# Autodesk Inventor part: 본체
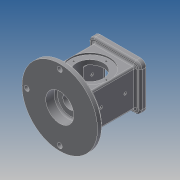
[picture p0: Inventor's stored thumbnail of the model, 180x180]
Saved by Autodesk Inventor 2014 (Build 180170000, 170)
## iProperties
Created: 2019-08
Part Number: 본체
Material: Generic
Document SubType Name: Modeling
Designer: kb542
Density: 1 g/cm^3
Appearance: Default
Author: kb542
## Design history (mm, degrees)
sketch "스케치1"
  geometry: C1 r 67.5 at (0, 0); 1 further point
  constraints: 1 centre point, 1 coincident
  dimensions: "d0" = 135 diameter of C1
extrude "돌출1" new body sketch "스케치1" distance "d1" = 10; taper "d2" = 0 deg
sketch "스케치2"
  geometry: L1 (-37, -33)-(37, -33); L2 (37, -33)-(37, 33); L3 (37, 33)-(-37, 33); L4 (-37, 33)-(-37, -33); L5 (-37, -33)-(37, 33); L6 (37, -33)-(-37, 33); C1 r 67.5 at (0, 0) reference
  constraints: 12 end point, 2 midpoint, 2 parallel, 1 horizontal, 1 perpendicular
  dimensions: "d3" = 74 distance of L2.end L3.end; "d4" = 66 distance of L1.end L2.end
node "작업 평면1"
sketch "스케치3" dims "d6" = 118
  geometry: 3 further points
  constraints: 2 horizontal alignment, 1 coincident, 2 other
feature "엠보싱1" sketch "스케치3" dims "d7" = 0.5, "d8" = 0
extrude "돌출2" join sketch "스케치2" distance "d9" = 98; taper "d10" = 0 deg
sketch "스케치4"
  geometry: L1 (-37, -33)-(37, -33) reference; L2 (37, -33)-(37, 33) reference; L3 (37, 33)-(-37, 33) reference; L4 (-37, 33)-(-37, -33) reference; L5 (-46, -41)-(46, -41); L6 (46, -41)-(46, 41); L7 (46, 41)-(-46, 41); L8 (-46, 41)-(-46, -41); L9 (-46, -41)-(46, 41); L10 (46, -41)-(-46, 41); 1 further point
  constraints: 12 end point, 2 midpoint, 2 parallel, 1 horizontal, 1 perpendicular
  dimensions: "d11" = 92 distance of L6.end L7.end; "d12" = 82 distance of L5.end L6.end
extrude "돌출3" join sketch "스케치4" distance "d13" = 10; taper "d14" = 0 deg
sketch "스케치5"
  geometry: 2 further points
  constraints: 1 vertical alignment
  dimensions: "d15" = 54 distance of point (37, -10) point (37, 44)
hole "구멍1" sketch "스케치5" at (37, 44) diameter "d16" = 48; stored, may be unused: countersink angle "d20" = 90 deg, drill point angle "d22" = 118 deg; dims "d17" = 6, "d18" = 4, "d19" = 2, "d21" = 8
sketch "스케치6"
  geometry: C1 r 24 at (37, 44) reference; 2 further points
  constraints: 1 coincident
hole "구멍2" sketch "스케치6" at (37, 44) diameter "d23" = 70; stored, may be unused: countersink angle "d27" = 90 deg, drill point angle "d29" = 0 deg; dims "d24" = 6, "d25" = 4, "d26" = 2, "d28" = 3
sketch "스케치7"
  geometry: C1 r 24 at (37, 44) reference; 2 further points
  constraints: 1 coincident
hole "구멍3" sketch "스케치7" at (37, 44) diameter "d30" = 70; stored, may be unused: countersink angle "d34" = 90 deg, drill point angle "d36" = 0 deg; dims "d31" = 6, "d32" = 4, "d33" = 2, "d35" = 3
sketch "스케치8"
  geometry: C1 r 67.5 at (0, 0) reference; 1 further point
  constraints: 1 coincident
hole "구멍4" sketch "스케치8" at (0, 0) diameter "d37" = 25; stored, may be unused: countersink angle "d41" = 90 deg, drill point angle "d43" = 118 deg; dims "d38" = 6, "d39" = 4, "d40" = 2, "d42" = 3
sketch "스케치9"
  geometry: C1 r 67.5 at (0, 0) reference; 1 further point
  constraints: 1 coincident
hole "구멍5" sketch "스케치9" at (0, 0) diameter "d44" = 50; stored, may be unused: countersink angle "d48" = 90 deg, drill point angle "d50" = 0 deg; dims "d45" = 6, "d46" = 4, "d47" = 2, "d49" = 18
sketch "스케치10"
  geometry: L1 (-22, -22)-(22, -22); L2 (22, -22)-(22, 22); L3 (22, 22)-(-22, 22); L4 (-22, 22)-(-22, -22); L5 (-22, -22)-(22, 22); L6 (22, -22)-(-22, 22); C1 r 12.5 at (0, 0) reference
  constraints: 12 end point, 2 midpoint, 2 parallel, 2 perpendicular, 1 horizontal
  dimensions: "d51" = 44 distance of L2.end L3.end
extrude "돌출4" cut sketch "스케치10" distance "d52" = 82; taper "d53" = 0 deg
sketch "스케치11"
  geometry: L1 (22, 22)-(22, -22) reference; L2 (22, -22)-(-22, -22) reference; L3 (-22, -22)-(-22, 22) reference; L4 (-22, 22)-(22, 22) reference; L5 (-26, -26)-(26, -26); L6 (26, -26)-(26, 26); L7 (26, 26)-(-26, 26); L8 (-26, 26)-(-26, -26); L9 (-26, -26)-(26, 26); L10 (26, -26)-(-26, 26); 1 further point
  constraints: 12 end point, 2 midpoint, 2 parallel, 2 perpendicular, 1 horizontal
  dimensions: "d54" = 52 distance of L7.end L5.start
extrude "돌출5" cut sketch "스케치11" distance "d55" = 8; taper "d56" = 0 deg
sketch "스케치12"
  geometry: C1 r 24 at (0, 0) reference; 2 further points
  constraints: 1 vertical alignment
  dimensions: "d57" = 29 distance of C1.centre point (0, 29)
hole "구멍6" sketch "스케치12" at (0, 29) diameter "d58" = 3.242; stored, may be unused: countersink angle "d62" = 90 deg, drill point angle "d64" = 118 deg; dims "d59" = 4, "d60" = 4, "d61" = 2, "d63" = 6
sketch "스케치13"
  geometry: C1 r 67.5 at (0, 0) reference; 3 further points
  constraints: 2 vertical alignment, 1 horizontal alignment
  dimensions: "d68" = 59 distance of C1.centre point (-59, 0); "d69" = 59 distance of C1.centre point (0, 59); "d70" = 59 distance of point (0, -59) C1.centre
hole "구멍7" sketch "스케치13" at (0, 59), (0, -59), (-59, 0) diameter "d71" = 9; stored, may be unused: countersink angle "d75" = 90 deg, drill point angle "d77" = 118 deg; dims "d72" = 9, "d73" = 4, "d74" = 2, "d76" = 6
sketch "스케치14"
  geometry: 3 further points
  constraints: 2 vertical alignment
  dimensions: "d78" = 37 distance of point (33, -10) point (33, 27); "d79" = 43 distance of point (33, 70) point (33, 27)
hole "구멍8" sketch "스케치14" at (33, 27), (33, 70) diameter "d80" = 4.917; stored, may be unused: countersink angle "d84" = 90 deg, drill point angle "d86" = 118 deg; dims "d81" = 9, "d82" = 4, "d83" = 2, "d85" = 6
fillet "모깎기1" dims "d87" = 10, "d88" = 3
fillet "모깎기2" dims "d89" = 3
chamfer "모따기1" distance "d90" = 1; stored, may be unused: second distance "d91" = 2, angle "d92" = 45 deg
fillet "모깎기3" dims "d93" = 3
sketch "스케치15"
  geometry: A1 r 10 centre (-36, -31) between (-46, -31) and (-36, -41) reference; A2 r 10 centre (36, -31) between (36, -41) and (46, -31) reference; A3 r 10 centre (36, 31) between (46, 31) and (36, 41) reference; A4 r 10 centre (-36, 31) between (-36, 41) and (-46, 31) reference; 5 further points
  constraints: 4 coincident
hole "구멍9" sketch "스케치15" at (-36, 31), (36, 31), (36, -31), (-36, -31) diameter "d94" = 3.242; stored, may be unused: countersink angle "d98" = 90 deg, drill point angle "d100" = 118 deg; dims "d95" = 4, "d96" = 4, "d97" = 2, "d99" = 6
chamfer "모따기2" distance "d101" = 3; stored, may be unused: second distance "d102" = 2, angle "d103" = 45 deg
node "솔리드1"
pattern_circular "원형 패턴1" dims angle "d66" = 360 deg
mirror "대칭1"
other parameters: "d5" = 0.5
